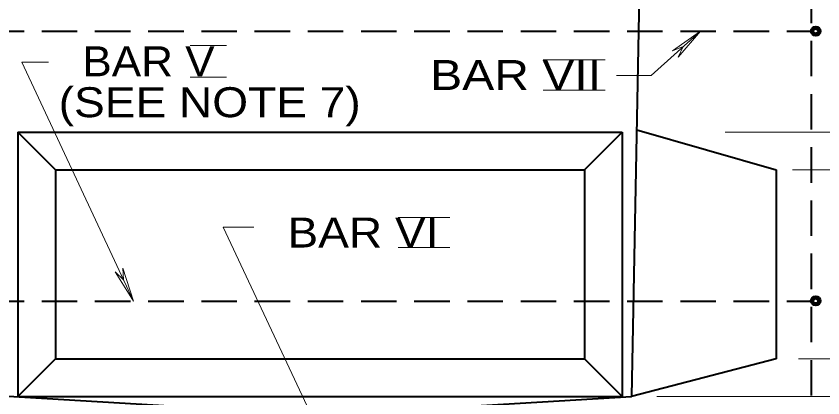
# Model space of a CAD drawing. Extents: x 312583 to 312854, y 144419 to 144597.
# Drawn here: x 312703.67 to 312724.13, y 144457.33 to 144467.02 of the extents above; entities that cross this region are included whole.
import ezdxf

# ---------------------------------------------------------------- set-up
doc = ezdxf.new("R2010")
doc.units = 0
doc.header["$LTSCALE"] = 0.3
doc.linetypes.add('MEDIUM_DASHED', pattern=[4.5, 3, -1.5])
doc.layers.add('1', color=7, linetype='Continuous', lineweight=25)
doc.layers.add('2', color=7, linetype='Continuous', lineweight=13)

msp = doc.modelspace()

# ---------------------------------------------------------------- linework, layer by layer
at = {"layer": '1', "lineweight": 40}
for p, q in [((312720.0164, 144496.4194), (312719.2804, 144457.3654)), ((312703.7094, 144464.0737), (312719.0427, 144464.0737)), ((312703.7094, 144464.0737), (312703.7094, 144457.3654)), ((312704.6677, 144463.1154), (312703.7094, 144464.0737)), ((312718.0844, 144463.1154), (312719.0427, 144464.0737)), ((312719.0427, 144464.0737), (312719.0427, 144457.3654)), ((312719.4107, 144464.135), (312722.9527, 144463.1154)), ((312704.6677, 144463.1154), (312718.0844, 144463.1154)), ((312704.6677, 144463.1154), (312704.6677, 144458.3237)), ((312718.0844, 144463.1154), (312718.0844, 144458.3237)), ((312722.9527, 144463.1154), (312722.9527, 144458.3237)), ((312704.6677, 144458.3237), (312703.7094, 144457.3654)), ((312704.6677, 144458.3237), (312718.0844, 144458.3237)), ((312719.0427, 144457.3654), (312718.0844, 144458.3237)), ((312722.9527, 144458.3237), (312719.2804, 144457.3654)), ((312711.376, 144456.89), (312703.464, 144457.3654)), ((312703.7094, 144457.3654), (312719.0427, 144457.3654)), ((312711.376, 144456.89), (312719.2804, 144457.3654))]:
    msp.add_line(p, q, dxfattribs=at)
at = {"layer": '1', "linetype": 'MEDIUM_DASHED', "lineweight": 40}
for p, q in [((312723.8344, 144494.7404), (312723.8344, 144452.9187)), ((312698.9177, 144466.6344), (312723.8344, 144466.6344)), ((312698.9177, 144459.788), (312723.8344, 144459.788))]:
    msp.add_line(p, q, dxfattribs=at)
at = {"layer": '1', "lineweight": 40}
for centre, radius in [((312723.9513, 144466.6363), 0.1198), ((312723.9513, 144466.6363), 0.0838), ((312723.9513, 144466.6363), 0.0587), ((312723.9513, 144459.7909), 0.1198), ((312723.9513, 144459.7909), 0.0838), ((312723.9513, 144459.7909), 0.0587)]:
    msp.add_circle(centre, radius, dxfattribs=at)
at = {"layer": '2'}
for p, q in [((312721.0284, 144466.6344), (312720.3154, 144466.136)), ((312721.0284, 144466.6344), (312720.461, 144465.975)), ((312708.0794, 144466.2723), (312709.007, 144466.2723)), ((312720.3154, 144466.136), (312720.5914, 144466.2434)), ((312720.461, 144465.975), (312720.5914, 144466.2434)), ((312704.4914, 144465.8524), (312703.809, 144465.8524)), ((312703.809, 144465.8524), (312706.6457, 144459.788)), ((312717.034, 144465.909), (312718.6134, 144465.909)), ((312708.0794, 144465.4655), (312709.007, 144465.4655)), ((312717.034, 144465.1421), (312718.6134, 144465.1421)), ((312721.657, 144464.0737), (312733.203, 144464.0737)), ((312723.3667, 144463.1154), (312738.1787, 144463.1154)), ((312713.3617, 144461.9113), (312714.6727, 144461.9113)), ((312713.3617, 144461.145), (312714.6727, 144461.145)), ((312706.178, 144460.5317), (312706.3927, 144460.3247)), ((312706.6457, 144459.788), (312706.178, 144460.5317)), ((312706.3774, 144460.6237), (312706.3927, 144460.3247)), ((312706.6457, 144459.788), (312706.3774, 144460.6237)), ((312723.5124, 144458.3237), (312728.005, 144458.3237)), ((312719.9244, 144457.3654), (312732.858, 144457.3654))]:
    msp.add_line(p, q, dxfattribs=at)
for points in [[(312718.897, 144465.5074), (312719.7787, 144465.5074), (312721.0284, 144466.6344)], [(312709.697, 144461.6664), (312708.9227, 144461.6664), (312711.376, 144456.4377)]]:
    msp.add_lwpolyline(points, dxfattribs=at)

# ---------------------------------------------------------------- texts
for s, width, p in [('BAR V', 1.1, (312705.3479, 144465.4913)), ('BAR VII', 1.2, (312714.1698, 144465.1435)), ('(SEE NOTE 7)', 1.15, (312704.7461, 144464.4534)), ('BAR VI', 1.15, (312710.5505, 144461.1465))]:
    msp.add_text(s, height=0.76, dxfattribs=dict(at, width=width)).set_placement(p)

doc.saveas('drawing.dxf')
